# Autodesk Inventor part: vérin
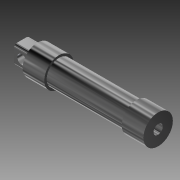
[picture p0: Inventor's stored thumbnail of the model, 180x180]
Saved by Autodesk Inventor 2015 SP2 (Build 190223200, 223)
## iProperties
Created: 2015-08
Part Number: vérin
Material: Générique
Document SubType Name: Modeling
Designer: Dominique
Density: 1 g/cm^3
Appearance: Sans teinte
Author: Dominique
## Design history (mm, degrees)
sketch "Esquisse1"
  geometry: L1 (0, 0)-(78, 0); L2 (78, 0)-(78, 8); L3 (64, 8)-(14, 8); L4 (0, 8)-(0, 0); L5 (14, 8)-(14, 9.5); L6 (14, 9.5)-(0, 9.5); L7 (0, 9.5)-(0, 8); L8 (64, 8)-(64, 9.5); L9 (64, 9.5)-(78, 9.5); L10 (78, 9.5)-(78, 8)
  constraints: 20 end point, 4 parallel, 1 horizontal, 1 perpendicular
  dimensions: "d0" = 78 distance of L4.start L2.end; "d1" = 8 distance of L2.end L1.end; "d2" = 14 distance of L6.end L5.end; "d3" = 1.5 distance of L3.end L5.end; "d4" = 14 distance of L8.end L9.end; "d5" = 1.5 distance of L3.start L8.end
revolve "Révolution1" sketch "Esquisse1" stored, may be unused: angle "d6" = 90 deg
sketch "Esquisse2"
  geometry: L1 (0, 9.5)-(0, -9.5) reference; L2 (0, 6)-(10, 6); L3 (10, 6)-(10, -6); L4 (10, -6)-(0, -6); L5 (0, -6)-(0, 6); 1 further point
  constraints: 8 end point, 2 parallel, 1 horizontal, 1 perpendicular, 1 point on line
  dimensions: "d7" = 10 distance between parallel lines of L3 L1; "d8" = 6 distance from line of L2 point (0, 0); "d9" = 12 distance between parallel lines of L4 L2
extrude "Extrusion1" join sketch "Esquisse2" stored distance "d10" = 10; taper "d11" = 0 deg
fillet "Congé1" dims "d12" = 2
sketch "Esquisse3"
  geometry: 1 further point
sketch "Esquisse4"
  geometry: L1 (-10, 4)-(0, 4) reference; L2 (-10, 4)-(-10, -4) reference; C1 r 3 at (-5, 0); 1 further point
  constraints: 1 centre point
  dimensions: "d13" = 6 diameter of C1
extrude "Extrusion2" cut sketch "Esquisse4" distance "d14" = 10; taper "d15" = 0 deg
sketch "Esquisse5"
  geometry: C1 r 3 at (0, 0); 1 further point
  constraints: 1 centre point, 1 coincident
  dimensions: "d16" = 6 diameter of C1
extrude "Extrusion3" cut sketch "Esquisse5" distance "d17" = 50; taper "d18" = 0 deg
node "Solide1"
